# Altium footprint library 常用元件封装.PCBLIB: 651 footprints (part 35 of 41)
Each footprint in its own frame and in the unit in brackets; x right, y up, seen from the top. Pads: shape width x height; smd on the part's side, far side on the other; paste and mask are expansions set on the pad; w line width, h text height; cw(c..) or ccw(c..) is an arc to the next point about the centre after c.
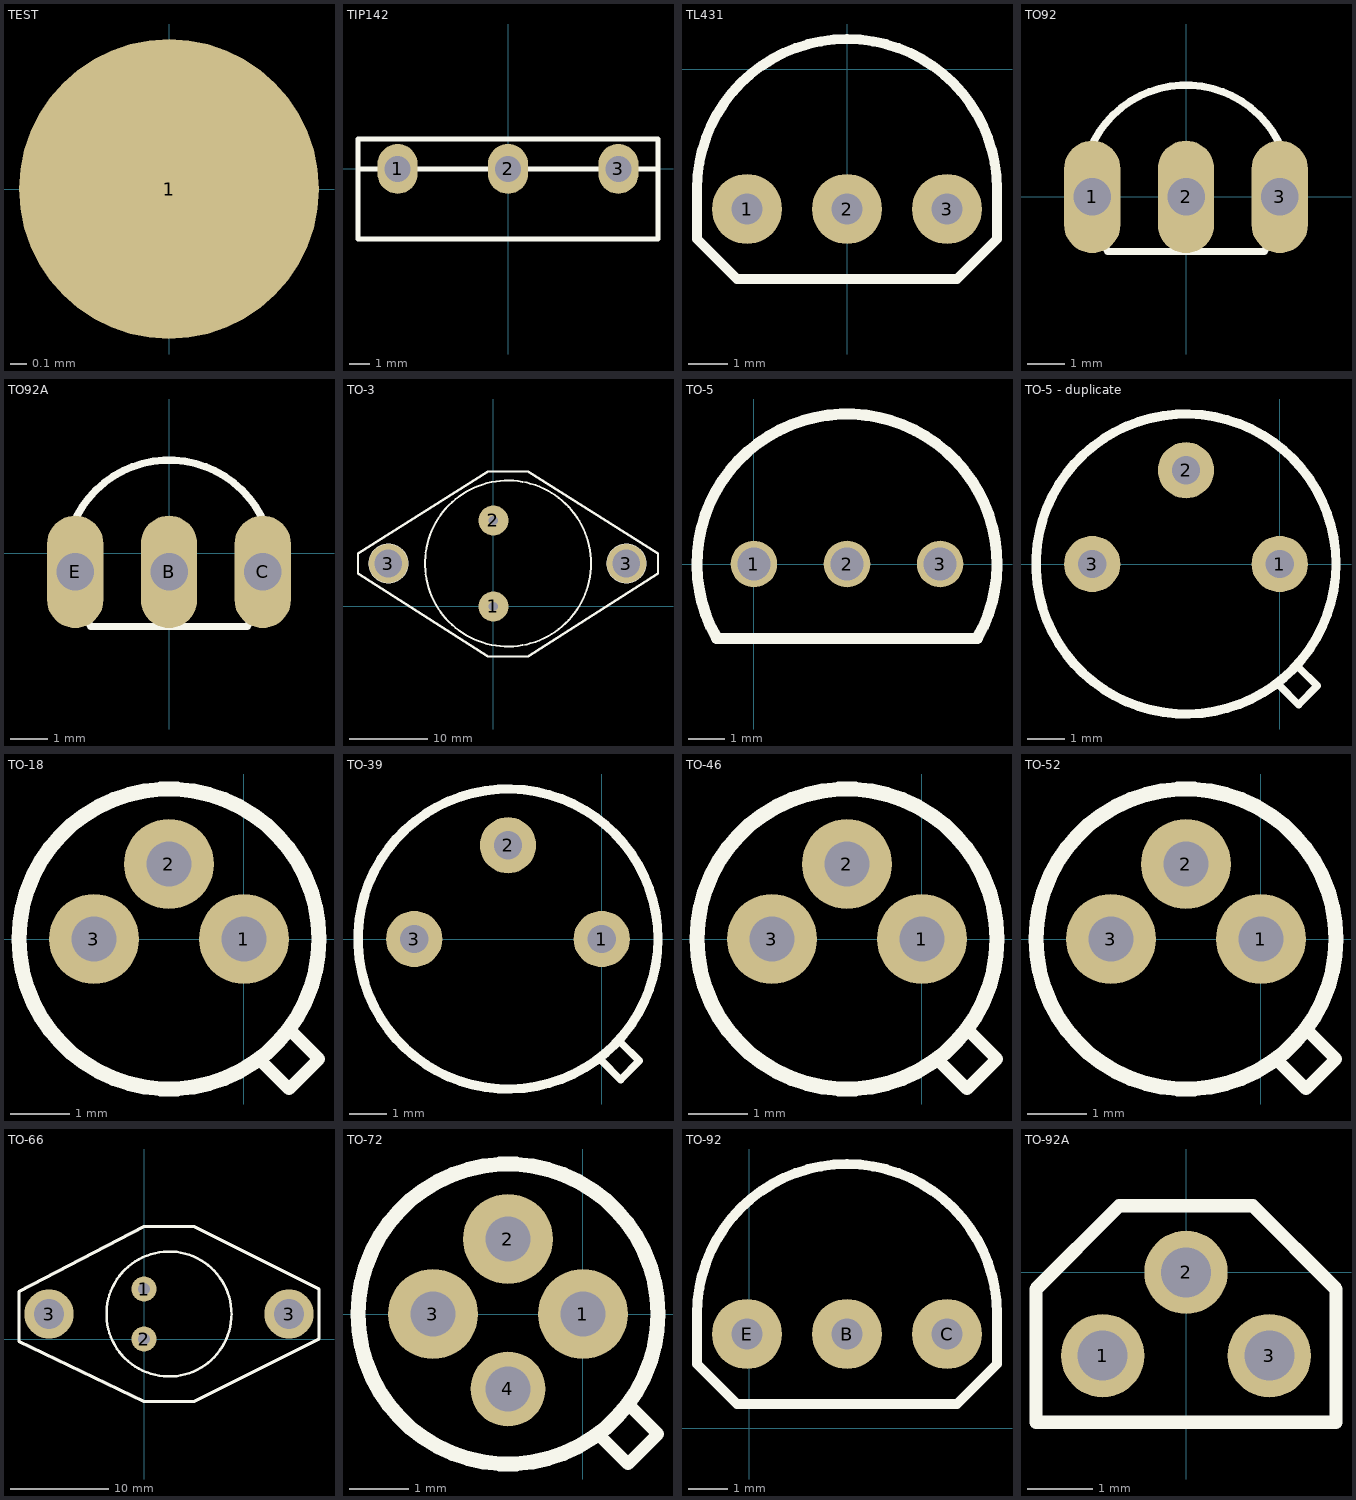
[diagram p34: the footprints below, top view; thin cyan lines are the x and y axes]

## TEST [mil]
pads (1):
  round 70 smd: 1(0,0)

## TIP142 [mil]
pads (3):
  oval 79x98 hole 51: 1(-217,0) 2(0,0) 3(217,0)
TopOverlay:
  lines w10: -295,0 295,0 ; -295,-138 -295,59 295,59 295,-138 -295,-138

## TL431 [mil]
pads (3):
  round 70 hole 31.5: 1(-100,-140) 2(0,-140) 3(100,-140)
TopOverlay:
  lines w10: -150,-170 -150,-120 cw(c0,-120) 150,-120 150,-170 110,-210 -110,-210 -150,-170

## TO92 [mil]
pads (3):
  oval 60x120 hole 40: 1(-100,0) 2(0,0) 3(100,0)
TopOverlay:
  lines w7.87: -102.76,49.85 cw(c0,8.33) 102.76,49.85 ; -89.08,-49.71 -83.33,-58.33 83.33,-58.33 89.08,-49.71

## TO92A [mil]
pads (3):
  oval 60x120 hole 40: B(0,-20) C(100,-20) E(-100,-20)
TopOverlay:
  lines w7.87: -102.76,29.85 cw(c0,-11.67) 102.76,29.85 ; -89.08,-69.71 -83.33,-78.33 83.33,-78.33 89.08,-69.71

## TO-3 [mm]
pads (4):
  round 3.81 hole 1.2: 1(0,0) 2(0,10.922)
  round 5 hole 3.5: 3(-13.335,5.461) 3(16.891,5.461)
TopOverlay:
  circle w0.254: c-13.335,5.461 r2.413
  circle w0.254: c16.891,5.461 r2.413
  circle w0.254: c1.854,5.461 r10.541
  lines w0.305: -17.196,4.191 -17.196,6.731 -0.686,17.145 4.394,17.145 20.904,6.731 20.904,4.191 4.394,-6.35 -0.686,-6.35 -17.196,4.191

## TO-5 [mm]
pads (3):
  round 1.27 hole 0.9: 1(0,0) 2(2.54,0) 3(5.08,0)
TopOverlay:
  lines w0.305: -1.016,-2.032 cw(c2.54,0) 6.096,-2.032 -1.016,-2.032

## TO-5 - duplicate [mil]
pads (3):
  round 60 hole 30: 1(0,0) 2(-100,100) 3(-200,0)
TopOverlay:
  circle w10: c-100,0 r160
  lines w8: 0,-130 20,-150 40,-130 20,-110

## TO-18 [mil]
pads (3):
  round 60 hole 30: 1(0,0) 2(-50,50) 3(-100,0)
TopOverlay:
  circle w10: c-50,0 r100
  lines w8: 10,-80 30,-100 50,-80 30,-60

## TO-39 [mil]
pads (3):
  round 60 hole 30: 1(0,0) 2(-100,100) 3(-200,0)
TopOverlay:
  circle w10: c-100,0 r160
  lines w8: 0,-130 20,-150 40,-130 20,-110

## TO-46 [mil]
pads (3):
  round 60 hole 30: 1(0,0) 2(-50,50) 3(-100,0)
TopOverlay:
  circle w10: c-50,0 r100
  lines w8: 10,-80 30,-100 50,-80 30,-60

## TO-52 [mil]
pads (3):
  round 60 hole 30: 1(0,0) 2(-50,50) 3(-100,0)
TopOverlay:
  circle w10: c-50,0 r100
  lines w8: 10,-80 30,-100 50,-80 30,-60

## TO-66 [mm]
pads (4):
  round 2.54 hole 1.2: 1(0,5.08) 2(0,0)
  round 5 hole 3: 3(-9.652,2.54) 3(14.732,2.54)
TopOverlay:
  circle w0.254: c14.732,2.54 r2.032
  circle w0.254: c-9.652,2.54 r2.032
  circle w0.254: c2.54,2.54 r6.35
  lines w0.305: -12.7,-0.254 0,-6.35 5.08,-6.35 17.78,0 17.78,5.08 5.08,11.43 0,11.43 -12.7,4.826 -12.7,-0.254

## TO-72 [mil]
pads (4):
  round 60 hole 30: 1(0,0) 2(-50,50) 3(-100,0)
  round 50 hole 30: 4(-50,-50)
TopOverlay:
  circle w10: c-50,0 r100
  lines w8: 10,-80 30,-100 50,-80 30,-60

## TO-92 [mil]
pads (3):
  round 70 hole 31.5: B(98,94) C(198,94) E(-2,94)
TopOverlay:
  lines w10: -52,64 -12,24 208,24 248,64 248,114 ccw(c98,114) -52,114 -52,64

## TO-92A [mil]
pads (3):
  round 50 hole 30: 1(-50,-50) 2(0,0) 3(50,-50)
TopOverlay:
  lines w8: -90,-90 90,-90 90,-10 40,40 -40,40 -90,-10 -90,-90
